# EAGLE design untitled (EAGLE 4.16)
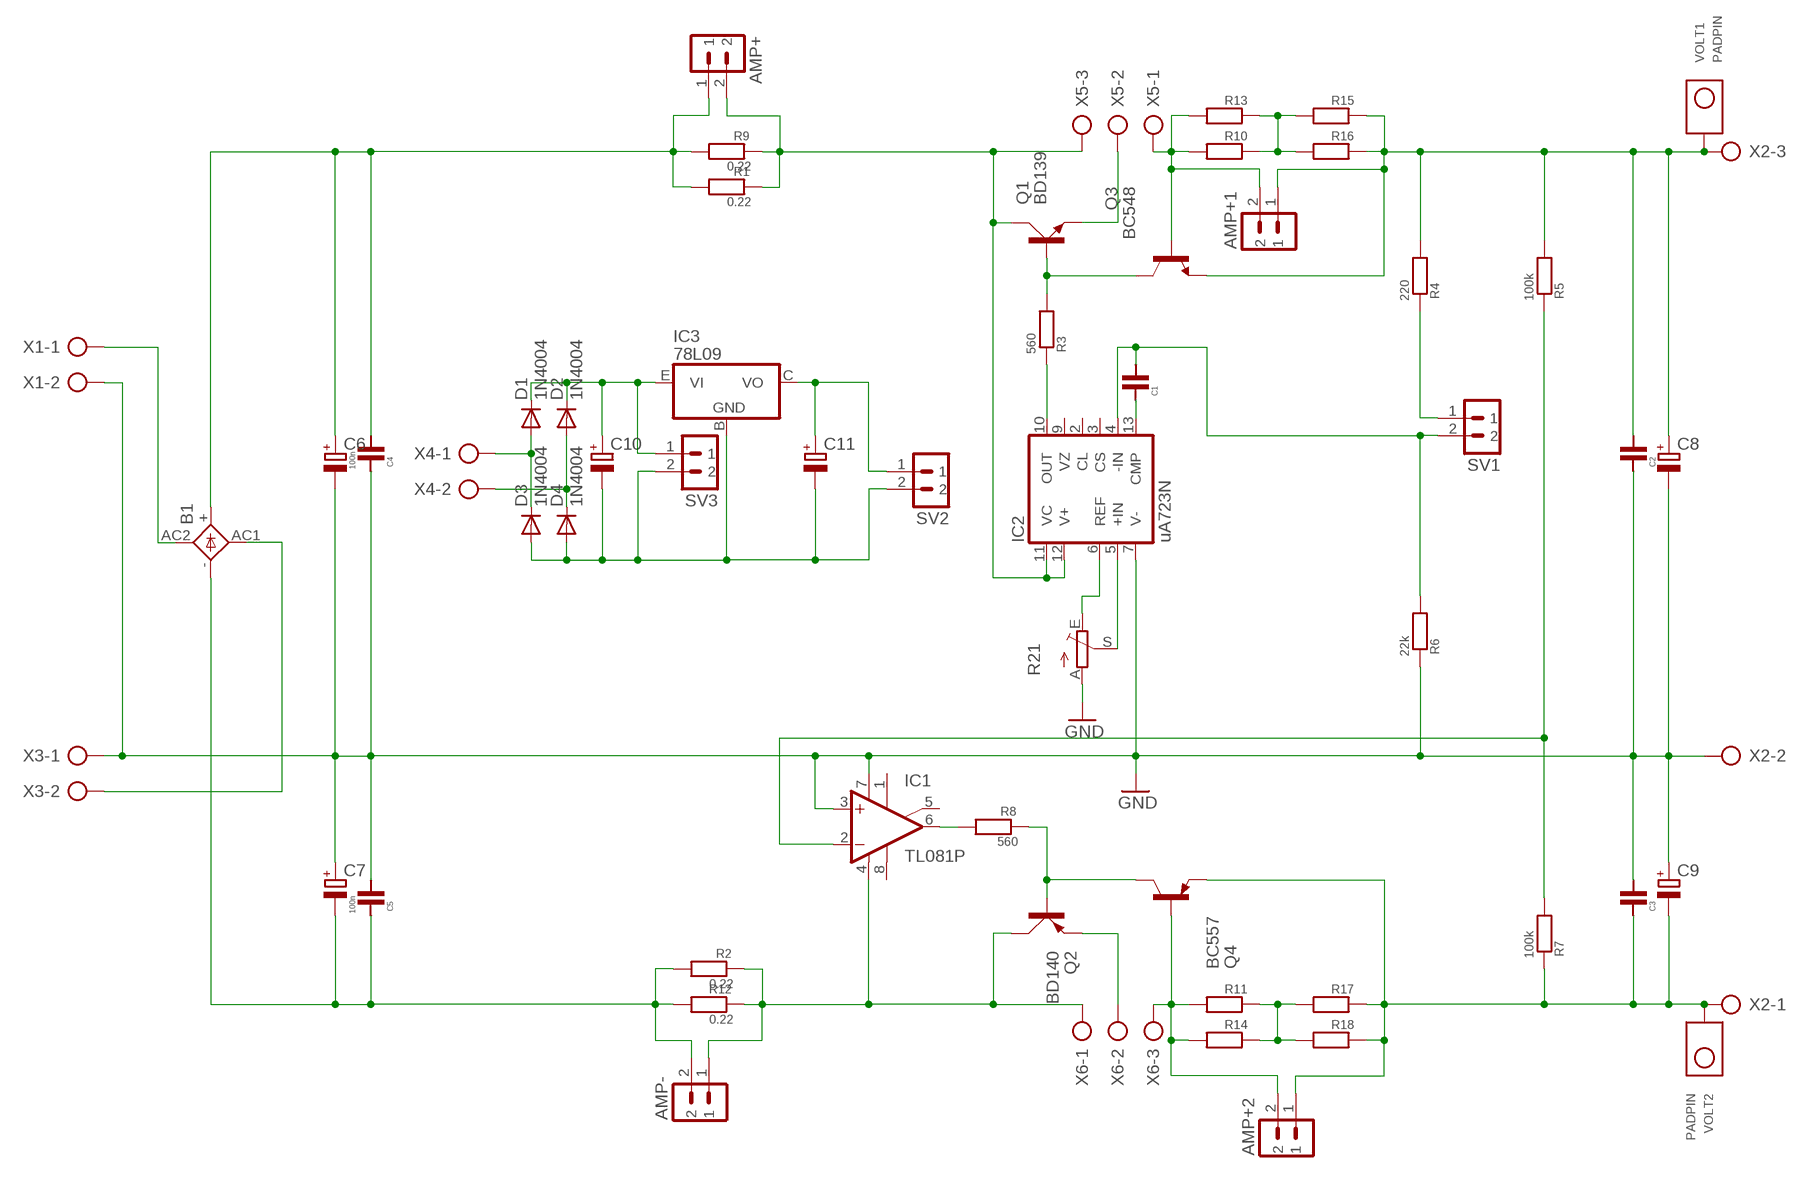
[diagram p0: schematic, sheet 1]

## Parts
AMP+  MA02-1  [MA02-1]
AMP+1  MA02-1  [MA02-1]
AMP+2  MA02-1  [MA02-1]
AMP-  MA02-1  [MA02-1]
B1  KBL  [KBL]
C1  CAP  [CAP]
C2  CAP  [CAP]
C3  CAP  [CAP]
C4  100n  CAP  [CAP]
C5  100n  CAP  [CAP]
C6  CPOL-EUE7.5-16  [E7,5-16]
C7  CPOL-EUE7.5-16  [E7,5-16]
C8  CPOL-EUE5-10.5  [E5-10,5]
C9  CPOL-EUE5-10.5  [E5-10,5]
C10  CPOL-EUE2.5-5  [E2,5-5]
C11  CPOL-EUE2.5-5  [E2,5-5]
D1  1N4004  [DO41-10]
D2  1N4004  [DO41-10]
D3  1N4004  [DO41-10]
D4  1N4004  [DO41-10]
IC1  TL081P  [DIL08]
IC2  uA723N  [DIL14]
IC3  78L09  78  [TO92-EBC]
Q1  BD139  [TO126AV]
Q2  BD140  [TO126AV]
Q3  BC548  [TO92-EBC]
Q4  BC557  [TO92-EBC]
R1  0.22  RES  [RES]
R2  0.22  RES  [RES]
R3  560  RES  [RES]
R4  220  RES  [RES]
R5  100k  RES  [RES]
R6  22k  RES  [RES]
R7  100k  RES  [RES]
R8  560  RES  [RES]
R9  0.22  RES  [RES]
R10  RES  [RES]
R11  RES  [RES]
R12  0.22  RES  [RES]
R13  RES  [RES]
R14  RES  [RES]
R15  RES  [RES]
R16  RES  [RES]
R17  RES  [RES]
R18  RES  [RES]
R21  TRIM_EU-CA6V  [CA6V]
SV1  MA02-1  [MA02-1]
SV2  MA02-1  [MA02-1]
SV3  MA02-1  [MA02-1]
VOLT1  PADPIN  [PAD]
VOLT2  PADPIN  [PAD]
X1  AK500/2  [AK500/2]
X2  AK500/3  [AK500/3]
X3  AK500/2  [AK500/2]
X4  AK500/2  [AK500/2]
X5  AK500/3  [AK500/3]
X6  AK500/3  [AK500/3]

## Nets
GND: C2.P$1 C3.P$2 C4.P$1 C5.P$2 C6.- C7.+ C8.- C9.+ IC1.3(+IN) IC1.7(V+) IC2.7(V-) R6.P$1 R21.A X1.2 X2.2 X3.1
N$1: IC2.6(REF) R21.E
N$2: IC2.5(+IN) R21.S
N$3: R4.P$1 SV1.1
N$4: C1.P$1 IC2.13(CMP)
N$6: IC1.2(-IN) R5.P$1 R7.P$2
N$7: IC2.10(OUT) R3.P$1
N$8: Q1.B Q3.C R3.P$2
N$9: Q1.E X5.2
N$11: AMP+1.2 Q3.B R10.P$2 R13.P$2 X5.1
N$12: AMP+1.1 C2.P$2 C8.+ Q3.E R4.P$2 R5.P$2 R15.P$1 R16.P$1 VOLT1.P$1 X2.3
N$14: C1.P$2 IC2.4(-IN) R6.P$2 SV1.2
N$15: AMP+2.2 Q4.B R11.P$2 R14.P$2 X6.3
N$16: Q2.E X6.2
N$18: Q2.B Q4.C R8.P$1
N$19: IC1.6(OUT) R8.P$2
N$20: AMP-.2 B1.- C5.P$1 C7.- R2.P$2 R12.P$2
N$21: B1.AC1(AC2) X3.2
N$22: B1.AC2(AC1) X1.1
N$24: D1.A D3.C X4.1
N$25: D2.A D4.C X4.2
N$26: C10.+ D1.C D2.C IC3.E(VI) SV3.1
N$27: AMP+.1 B1.+ C4.P$2 C6.+ R1.P$2 R9.P$2
N$28: C10.- C11.- D3.A D4.A IC3.B(GND) SV2.2 SV3.2
N$29: C11.+ IC3.C(VO) SV2.1
N$30: AMP+.2 IC2.11(VC) IC2.12(V+) Q1.C R1.P$1 R9.P$1 X5.3
N$31: AMP-.1 IC1.4(V-) Q2.C R2.P$1 R12.P$1 X6.1
N$32: R10.P$1 R13.P$1 R15.P$2 R16.P$2
N$33: AMP+2.1 C3.P$1 C9.- Q4.E R7.P$1 R17.P$1 R18.P$1 VOLT2.P$1 X2.1
N$34: R11.P$1 R14.P$1 R17.P$2 R18.P$2
Unconnected: IC1.1(ON1) IC1.5(ON2) IC1.8(OPT) IC2.2(CL) IC2.3(CS) IC2.9(VZ)

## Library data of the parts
AMP+ AMP+1 AMP+2 AMP- SV1-SV3 = divers:MA02-1: PIN HEADER
B1 = rectifier:KBL: DIOTEC RECTIFIER
C1-C5 = opory:CAP
C6-C11 = rcl:CPOL-EU: POLARIZED CAPACITOR, European symbol
D1-D4 = diode:1N4004: DIODE
IC1 = linear:TL081: OP AMP
IC2 = linear:*723: Positive VOLTAGE REGULATOR
IC3 = linear:78*: Positive VOLTAGE REGULATOR Source: http://cache.national.com/ds/LM/LM78L05.pdf http://www.fairchildsemi.com/ds/LM/LM7805.pdf
Q1 = transistor-power:BD139: NPN TRANSISTOR
Q2 = transistor-power:BD140: PNP TRANSISTOR
Q3 = transistor-npn:BC548*: NPN Transistor
Q4 = transistor-pnp:BC557*: PNP Transistror
R1-R18 = opory:RES
R21 = pot:TRIM_EU-: POTENTIOMETER
VOLT1 VOLT2 = pady:PADPIN
X1 X3 X4 = con-ptr500:AK500/2: CONNECTOR
X2 X5 X6 = con-ptr500:AK500/3: CONNECTOR

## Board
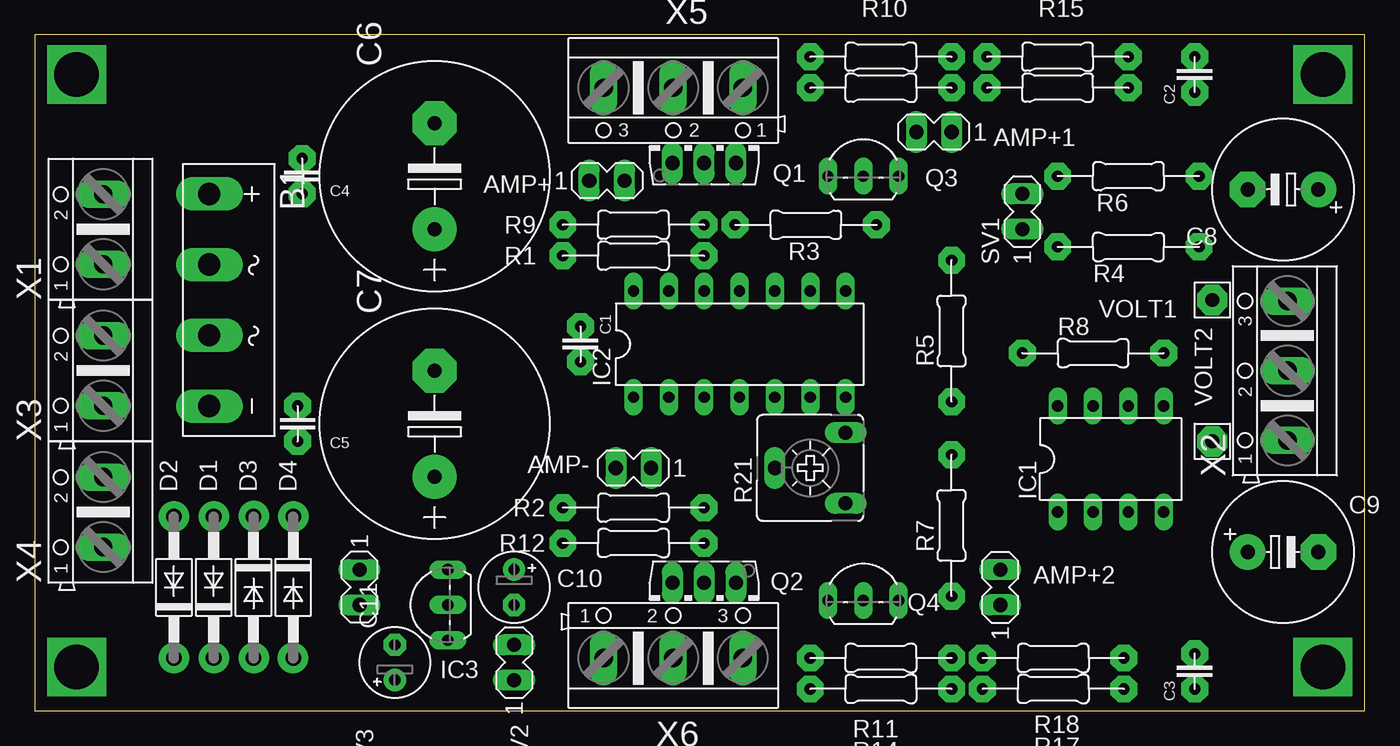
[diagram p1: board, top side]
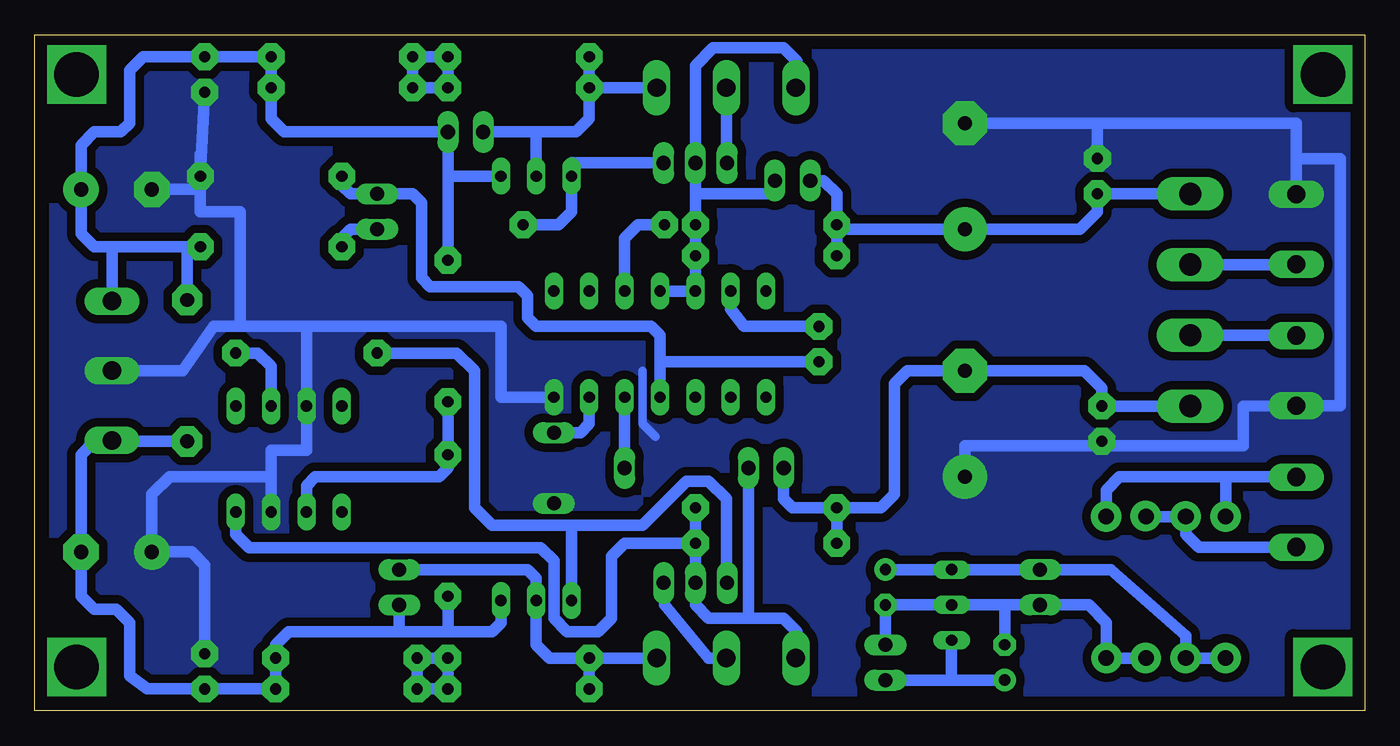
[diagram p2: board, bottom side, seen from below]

Size 95.56 x 48.57 mm. Coordinates in mm from the lower left corner, seen from the top.
Outline: 0,0 95.56,0 95.56,48.57 0,48.57 0,0
Copper layers (1*16): Top 0.035mm / dielectric 1.5mm / Bottom 0.035mm
Design rules "default": minimum track width 10mil, minimum drill 24mil, track to track 8mil, track to pad 8mil, pad to pad 8mil, via to via 8mil, smd to smd 8mil, copper to edge 40mil, drill to drill 8mil, minimum pad ring 10mil, minimum via ring 8mil, stop-mask expansion 4mil, vias tented up to drill 0mil, thermal gap 10mil

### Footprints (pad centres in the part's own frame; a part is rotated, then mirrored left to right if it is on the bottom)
MA02-1 = drill 1.016 long: 1 -2.54,0; 2 0,0
KBL = drill 1.6 long: + -7.62,-1.27; - 7.62,-1.27; AC1 2.54,-1.27; AC2 -2.54,-1.27
CAP = drill 0.8 pad 1.93 octagon: P$1 -1.27,0; P$2 1.27,0
E7,5-16 = drill 1.016 pad 3.15 round: + -3.81,0 | drill 1.016 pad 3.15 octagon: - 3.81,0
E5-10,5 = drill 1.016 pad 2.54 round: + -2.54,0 | drill 1.016 pad 2.54 octagon: - 2.54,0
E2,5-5 = drill 0.813 pad 1.6 round: + -1.27,0 | drill 0.813 pad 1.6 octagon: - 1.27,0
DO41-10 = drill 1.118 round: A 5.08,0; C -5.08,0
DIL08 = drill 0.813 long: 1 -3.81,-3.81; 2 -1.27,-3.81; 3 1.27,-3.81; 4 3.81,-3.81; 5 3.81,3.81; 6 1.27,3.81; 7 -1.27,3.81; 8 -3.81,3.81
DIL14 = drill 0.813 long: 1 -7.62,-3.81; 2 -5.08,-3.81; 3 -2.54,-3.81; 4 0,-3.81; 5 2.54,-3.81; 6 5.08,-3.81; 7 7.62,-3.81; 8 7.62,3.81; 9 5.08,3.81; 10 2.54,3.81; 11 0,3.81; 12 -2.54,3.81; 13 -5.08,3.81; 14 -7.62,3.81
TO92-EBC = drill 0.813 long: B 0,-1.27; C -2.54,-1.27; E 2.54,-1.27
TO126AV = drill 1.016 long: B 2.286,-1.27; C 0,-1.27; E -2.286,-1.27
RES = drill 0.8 pad 1.93 octagon: P$1 -5.08,0; P$2 5.08,0
CA6V = drill 1.016 long: A -2.54,-2.54; E 2.54,-2.54; S 0,2.54
PAD = drill 1 pad 2.184 octagon: P$1 0,0
AK500/2 = drill 1.321 long: 1 -2.515,0; 2 2.515,0
AK500/3 = drill 1.321 long: 1 -5.004,0; 2 0,0; 3 5.004,0

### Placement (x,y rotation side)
AMP+  42.38,38.09 0 top
AMP+1  63.34,41.59 180 top
AMP+2  69.37,10.15 90 top
AMP-  41.74,17.46 180 top
B1  13.81,29.52 270 top
C1  39.2,26.35 270 top
C2  83.34,45.72 90 top
C3  83.34,2.85 90 top
C4  19.2,38.41 270 top
C5  18.88,20.63 270 top
C6  28.73,38.41 90 top
C7  28.73,20.63 90 top
C8  89.69,37.46 180 top
C9  89.69,11.43 0 top
C10  34.44,8.88 270 top
C11  25.87,3.49 90 top
D1  12.85,8.88 90 top
D2  10,8.88 90 top
D3  15.71,8.88 270 top
D4  18.57,8.88 270 top
IC1  77.31,18.09 0 top
IC2  50.63,26.35 0 top
IC3  28.41,7.62 90 top
Q1  48.09,40.63 0 top
Q2  48.09,7.93 180 top
Q3  59.52,39.68 0 top
Q4  59.52,9.2 0 top
R1  43.02,32.7 180 top
R2  43.02,14.6 180 top
R3  55.4,34.92 0 top
R4  78.58,33.33 0 top
R5  65.88,27.3 90 top
R6  78.58,38.41 180 top
R7  65.88,13.33 90 top
R8  76.04,25.71 0 top
R9  43.02,34.92 180 top
R10  60.79,44.76 180 top
R11  60.79,3.81 180 top
R12  43.02,12.06 180 top
R13  60.79,46.98 180 top
R14  60.79,1.58 180 top
R15  73.5,44.76 180 top
R16  73.5,46.98 180 top
R17  73.18,3.81 180 top
R18  73.18,1.58 180 top
R21  55.71,17.46 90 top
SV1  70.96,37.14 90 top
SV2  34.44,4.76 90 top
SV3  23.33,7.62 270 top
VOLT1  84.61,29.52 90 top
VOLT2  84.61,19.36 0 top
X1  4.92,34.6 90 top
X2  90.01,24.44 90 top
X3  4.92,24.44 90 top
X4  4.92,14.28 90 top
X5  45.87,44.76 180 top
X6  45.87,3.81 0 top

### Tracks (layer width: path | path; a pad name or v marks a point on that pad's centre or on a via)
GND
  Bottom 0.61: 51.91,24.44 51.91,20.63 50.95,19.68
  Bottom 0.813: 4.92,39.68 1.74,39.68 1.74,21.93 X3.1 8.72,21.9 8.72,19.05 18.88,19.05 | 4.92,39.68 X1.2 | 19.2,42.22 4.92,42.22 4.92,39.68 | 19.2,42.22 C6.- | 18.88,19.05 28.73,19.05 C7.+ | 83.66,38.73 83.66,40 | 80.8,27.62 80.8,35.87 83.66,35.87 83.66,37.78 | 80.8,27.62 82.7,27.62 84.93,24.44 X2.2 | 78.58,16.82 85.88,16.82 87.15,15.55 C9.+ 84.29,11.43 83.34,10.47 C3.P$2 | 78.58,16.82 78.58,18.73 76.04,18.73 IC1.7 76.04,27.62 | 78.58,16.82 IC1.3 | 76.04,27.62 80.8,27.62 | 76.04,27.62 62.07,27.62 62.07,22.54 IC2.7 58.25,22.22 | 83.66,37.78 R6.P$1 | 83.66,38.73 83.66,39.05 | R6.P$1 83.66,38.73 | 19.2,42.22 C4.P$1 | 18.88,19.05 C5.P$2 | R6.P$1 C2.P$1 | C8.- 83.66,37.46 83.66,37.78
  pour Bottom (isolate 0.61, no thermals): -1.12,49.52 96.36,49.52 96.36,-0.64 -1.12,-0.64
N$1
  Bottom 0.813: R21.E 56.35,20 55.71,20.63 IC2.6
N$2
  Bottom 0.813: R21.S IC2.5
N$3
  Bottom 0.813: SV1.1 72.86,34.6 73.5,33.97 R4.P$1
N$4
  Bottom 0.813: C1.P$1 44.6,27.62 45.55,28.89 IC2.13
N$5  (via drill 3.2 pad 3.81)
  other vias: 3.01,3.17
N$6
  Bottom 0.813: R5.P$1 R7.P$2 65.88,17.46 66.51,16.82 75.4,16.82 76.04,16.19 IC1.2
N$7
  Bottom 0.813: R3.P$1 52.22,34.92 53.17,33.97 IC2.10
N$8
  Bottom 0.813: Q1.B 56.98,39.37 Q3.C 56.98,35.87 57.94,34.92 R3.P$2
N$9
  Bottom 0.813: Q1.E 45.87,39.68 X5.2
N$10  (via drill 3.2 pad 3.81)
  other vias: 3.01,45.72
N$11
  Bottom 0.813: 59.52,41.59 Q3.B | 50.63,44.76 X5.1 R10.P$2 | R10.P$2 R13.P$2 | 59.52,41.59 AMP+1.2 | 59.52,41.59 56.67,41.59 55.71,42.54 R10.P$2
N$12
  Bottom 0.813: 90.01,33.33 X2.3 | 90.01,33.33 91.28,33.33 92.23,34.28 C8.+ 92.23,40.63 91.28,41.59 89.37,41.59 88.73,42.22 88.73,46.03 87.78,46.98 C2.P$2 R16.P$1 | 90.01,33.33 R4.P$2 | R4.P$2 83.66,33.65 | R4.P$2 84.61,33.33 VOLT1.P$1 | R5.P$2 65.88,38.41 | R15.P$1 R16.P$1 | R15.P$1 R16.P$1 | R15.P$1 78.58,42.54 77.62,41.59 AMP+1.1 65.88,38.41 | 65.88,38.41 Q3.E
N$13  (via drill 1 pad 2.18)
  other vias: 9.99,13.97
N$14
  Bottom 0.813: R6.P$2 73.5,37.78 72.86,37.14 SV1.2 68.42,37.14 67.78,36.51 67.78,31.11 67.15,30.48 60.79,30.48 60.16,29.84 60.16,28.25 59.52,27.62 51.27,27.62 50.63,26.98 50.63,25.08 | C1.P$2 50.63,25.08 | 50.63,25.08 IC2.4
N$15
  Bottom 0.813: X6.3 R11.P$2 | R11.P$2 58.57,3.81 59.52,4.76 Q4.B 59.52,9.52 60.16,10.15 AMP+2.2 | R11.P$2 R14.P$2
N$16
  Bottom 0.813: X6.2 47.14,3.81 50.32,7.62 50.32,9.2 Q2.E
N$17  (via drill 3.2 pad 3.81)
  other vias: 92.55,45.72
N$18
  Bottom 0.813: R8.P$1 71.27,25.39 71.27,25.71 65.24,25.71 63.97,24.44 63.97,14.6 62.7,13.33 56.98,13.33 | Q2.B 45.87,9.2 45.87,15.23 47.14,16.5 48.73,16.5 51.91,13.33 56.98,13.33 | 56.98,13.33 Q4.C
N$19
  Bottom 0.813: IC1.6 78.58,24.76 79.53,25.71 R8.P$2
N$20
  Bottom 0.813: B1.- C5.P$1 18.88,23.17 20.15,24.44 C7.- 32.85,24.44 33.81,23.49 33.81,15.55 34.76,14.6 R2.P$2 | R2.P$2 R12.P$2 | R2.P$2 41.11,14.6 41.74,15.23 AMP-.2
N$21
  Bottom 0.813: B1.AC1 4.92,26.98 X3.2
N$22
  Bottom 0.813: B1.AC2 4.92,32.06 X1.1
N$23  (via drill 3.2 pad 3.81)
  other vias: 92.55,3.17
N$24
  Bottom 0.813: D1.A D3.C | D1.A 13.17,13.96 | X4.1 11.93,11.77 12.85,12.7 D1.A
N$25
  Bottom 0.813: D4.C 18.57,15.87 17.61,16.82 10,16.82 | 5.23,16.82 5.23,16.8 X4.2 4.92,16.82 10,16.82 | 10,16.82 D2.A
N$26
  Bottom 0.813: D2.C D1.C 12.85,5.39 18.25,10.15 SV3.1 IC3.E C10.+
N$27
  Bottom 0.813: B1.+ C4.P$2 19.2,35.87 20.47,34.6 C6.+ 37.62,34.6 37.62,34.92 R9.P$2 37.93,35.24 | AMP+.1 38.89,38.09 37.93,37.14 37.93,35.24 | 37.93,35.24 R1.P$2
N$28
  Bottom 0.813: D3.A D4.A 18.57,6.34 19.84,7.62 SV3.2 25.87,7.62 | 25.87,7.62 C11.- | 25.87,7.62 IC3.B C10.- SV2.2
N$29
  Bottom 0.813: C11.+ 29.68,2.22 | 29.68,2.22 SV2.1 | 29.68,2.22 IC3.C
N$30
  Bottom 0.813: IC2.11 IC2.12 R1.P$1 R9.P$1 48.09,37.14 | X5.3 40.79,44.76 40.79,46.67 41.74,47.62 46.82,47.62 48.09,46.35 48.09,39.68 48.41,39.37 Q1.C 48.09,37.14 | 48.09,37.14 42.38,37.14 AMP+.2
N$31
  Bottom 0.813: R12.P$1 53.17,12.06 54.13,11.11 54.13,6.66 55.08,5.71 57.3,5.71 58.25,6.66 58.25,10.79 59.21,11.74 80.16,11.74 81.12,12.7 IC1.4 | R12.P$1 Q2.C 48.09,7.62 47.14,6.66 44.28,6.66 | X6.1 40.79,3.81 40.79,5.71 41.74,6.66 44.28,6.66 | 44.28,6.66 AMP-.1 | R12.P$1 R2.P$1
N$32
  Bottom 0.813: R10.P$1 R13.P$1 R16.P$2 R15.P$2 R10.P$1
N$33
  Bottom 0.813: VOLT2.P$1 90.01,19.36 X2.1 91.28,19.36 92.23,18.41 C9.- 92.23,8.25 91.28,7.3 89.69,7.3 88.73,6.34 88.73,2.54 87.47,1.58 C3.P$1 R18.P$1 | 65.88,5.71 R7.P$1 | 65.88,5.71 69.37,5.71 | 69.37,5.71 77.31,5.71 78.26,4.76 R17.P$1 R18.P$1 | R18.P$1 77.94,1.58 77.94,1.9 | Q4.E 62.07,6.34 62.7,5.71 65.88,5.71 | 69.37,5.71 AMP+2.1
N$34
  Bottom 0.813: R11.P$1 R17.P$2 R18.P$2 R14.P$1 R11.P$1
N$35  (via drill 1 pad 2.18)
  other vias: 12.86,13.97
N$36  (via drill 1 pad 2.18)
  other vias: 15.74,14
N$37  (via drill 1 pad 2.18)
  other vias: 18.58,13.97
N$38  (via drill 1 pad 2.18)
  other vias: 18.56,3.82
N$39  (via drill 1 pad 2.18)
  other vias: 15.74,3.82
N$40  (via drill 1 pad 2.18)
  other vias: 12.86,3.82
N$41  (via drill 1 pad 2.18)
  other vias: 9.99,3.82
